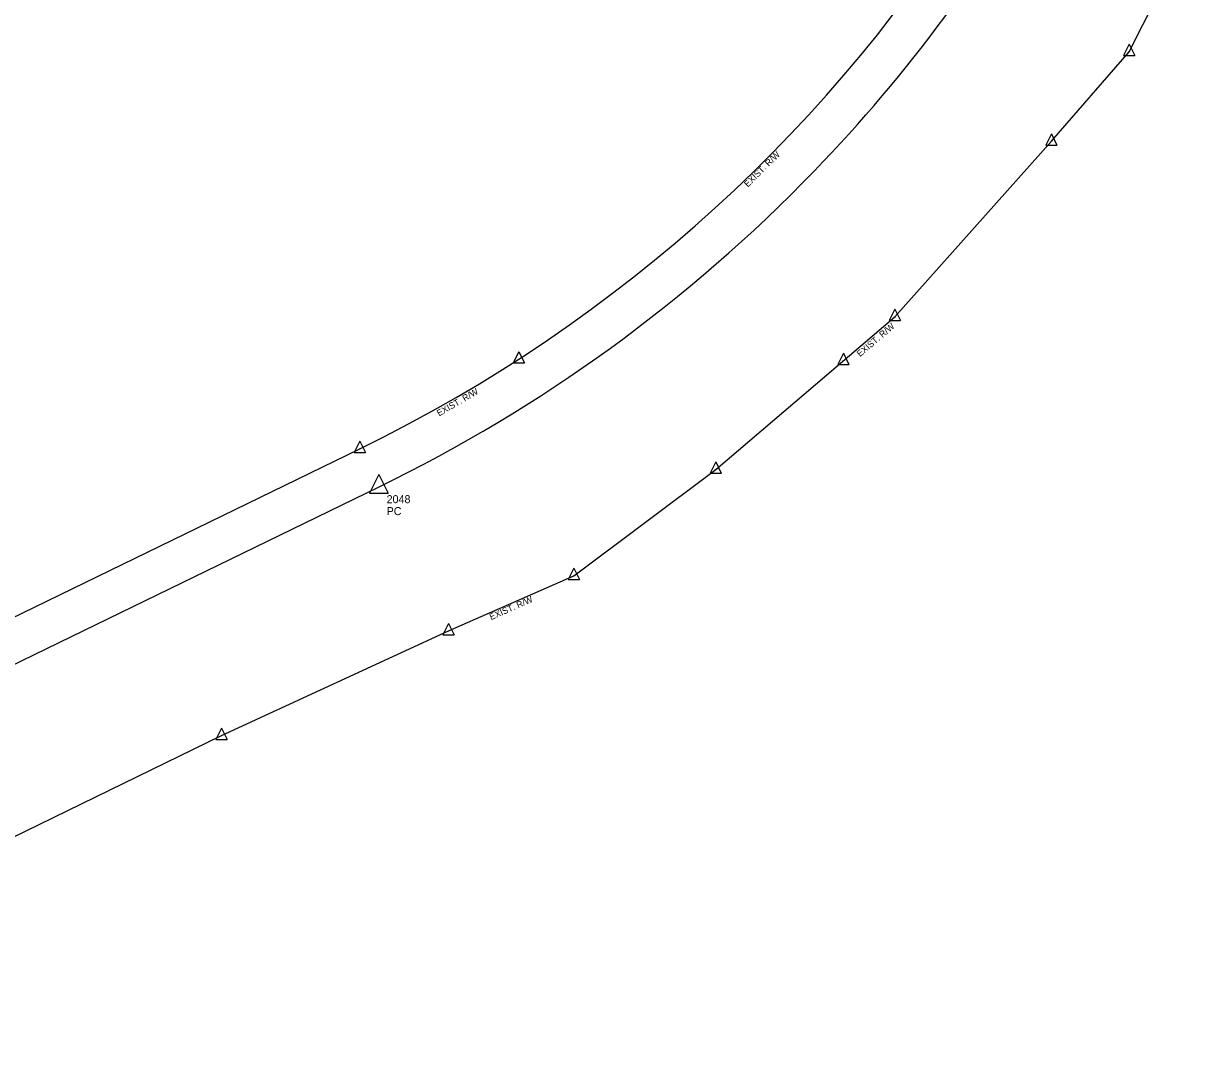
# Model space of a CAD drawing. Extents: x 1674300 to 1677561, y 225056 to 231852.
# Drawn here: x 1676229 to 1677337, y 227146 to 228119 of the extents above; entities that cross this region are included whole.
import ezdxf

# ---------------------------------------------------------------- set-up
doc = ezdxf.new("R2010")
doc.units = 0
for name, color, linetype in [('R_Annotation', 7, 'Continuous'), ('S_CAL_CORNER', 7, 'Continuous'), ('S_CAL_CORNER_ANNOT', 7, 'Continuous'), ('S_EXIST_ROW', 7, 'Continuous'), ('S_EXISTING_ALIGNMENT', 7, 'Continuous')]:
    doc.layers.add(name, color=color, linetype=linetype)

msp = doc.modelspace()

# ---------------------------------------------------------------- linework, layer by layer
at = {"layer": 'S_CAL_CORNER'}
for p, q in [((1676561.4, 227697), (1676552.6, 227679.3)), ((1676561.4, 227697), (1676552.6, 227679.3)), ((1676561.4, 227697), (1676552.6, 227679.3)), ((1676561.4, 227697), (1676552.6, 227679.3)), ((1676561.4, 227697), (1676570.1, 227679.3)), ((1676561.4, 227697), (1676570.1, 227679.3)), ((1676561.4, 227697), (1676570.1, 227679.3)), ((1676561.4, 227697), (1676570.1, 227679.3)), ((1676552.6, 227679.3), (1676570.1, 227679.3)), ((1676552.6, 227679.3), (1676570.1, 227679.3)), ((1676552.6, 227679.3), (1676570.1, 227679.3)), ((1676552.6, 227679.3), (1676570.1, 227679.3))]:
    msp.add_line(p, q, dxfattribs=at)
at = {"layer": 'S_EXIST_ROW'}
for p, q in [((1677264.8, 228093.1), (1677314.7, 228192.4)), ((1677264.8, 228100.2), (1677259.5, 228089.6)), ((1677264.8, 228100.2), (1677270.1, 228089.6)), ((1677192, 228009.2), (1677264.8, 228093.1)), ((1677259.5, 228089.6), (1677270.1, 228089.6)), ((1677264.8, 228093.1), (1677264.8, 228093.1)), ((1677045.3, 227844.6), (1677192, 228009.2)), ((1677192, 228016.3), (1677186.7, 228005.7)), ((1677192, 228016.3), (1677197.2, 228005.7)), ((1677192, 228009.2), (1677192, 228009.2)), ((1677186.7, 228005.7), (1677197.2, 228005.7)), ((1676877.3, 227701.7), (1677045.3, 227844.6)), ((1677045.3, 227851.7), (1677040, 227841.1)), ((1677040, 227841.1), (1677050.5, 227841.1)), ((1677045.3, 227851.7), (1677050.5, 227841.1)), ((1677045.3, 227844.6), (1677045.3, 227844.6)), ((1676692.6, 227812), (1676687.4, 227801.4)), ((1676692.6, 227812), (1676697.9, 227801.4)), ((1676997, 227810.6), (1676991.7, 227800)), ((1676997, 227810.6), (1677002.2, 227800)), ((1676687.4, 227801.4), (1676697.9, 227801.4)), ((1676692.6, 227804.9), (1676692.6, 227804.9)), ((1676991.7, 227800), (1677002.2, 227800)), ((1676996.9, 227803.5), (1676996.9, 227803.5)), ((1676060.3, 227485.8), (1676543.8, 227721)), ((1676543.8, 227728.1), (1676538.5, 227717.5)), ((1676543.8, 227728.1), (1676549, 227717.5)), ((1676543.8, 227721), (1676543.8, 227721)), ((1676538.5, 227717.5), (1676549, 227717.5)), ((1676877.3, 227708.8), (1676872, 227698.2)), ((1676877.3, 227708.8), (1676882.5, 227698.2)), ((1676744.4, 227601.9), (1676877.3, 227701.7)), ((1676872, 227698.2), (1676882.5, 227698.2)), ((1676877.3, 227701.7), (1676877.3, 227701.7)), ((1676744.4, 227609), (1676739.1, 227598.3)), ((1676744.4, 227609), (1676749.6, 227598.3)), ((1676626.9, 227550.2), (1676744.4, 227601.9)), ((1676739.1, 227598.3), (1676749.6, 227598.3)), ((1676744.4, 227601.9), (1676744.4, 227601.9)), ((1676626.9, 227557.3), (1676621.6, 227546.6)), ((1676626.9, 227557.3), (1676632.2, 227546.6)), ((1676414, 227452.1), (1676626.9, 227550.2)), ((1676621.6, 227546.6), (1676632.2, 227546.6)), ((1676626.9, 227550.2), (1676626.9, 227550.2)), ((1676414, 227459.2), (1676408.7, 227448.6)), ((1676414, 227459.2), (1676419.2, 227448.6)), ((1675784.5, 227145.9), (1676414, 227452.1)), ((1676408.7, 227448.6), (1676419.2, 227448.6)), ((1676414, 227452.1), (1676414, 227452.1))]:
    msp.add_line(p, q, dxfattribs=at)
for centre, radius in [((1677264.8, 228093.1), 0.18), ((1677264.8, 228093.1), 0.09), ((1677192, 228009.2), 0.18), ((1677192, 228009.2), 0.09), ((1677045.3, 227844.6), 0.18), ((1677045.3, 227844.6), 0.09), ((1676692.6, 227804.9), 0.18), ((1676692.6, 227804.9), 0.09), ((1676996.9, 227803.5), 0.18), ((1676996.9, 227803.5), 0.09), ((1676543.8, 227721), 0.18), ((1676543.8, 227721), 0.09), ((1676877.3, 227701.7), 0.18), ((1676877.3, 227701.7), 0.09), ((1676744.4, 227601.9), 0.18), ((1676744.4, 227601.9), 0.09), ((1676626.9, 227550.2), 0.18), ((1676626.9, 227550.2), 0.09), ((1676414, 227452.1), 0.18), ((1676414, 227452.1), 0.09)]:
    msp.add_circle(centre, radius, dxfattribs=at)
msp.add_arc((1675926.7, 228989.4), 1410.5, 295.9436, 0.8568, dxfattribs=at)
at = {"layer": 'S_EXISTING_ALIGNMENT'}
msp.add_line((1676112.4, 227466.7), (1676561.3, 227685), dxfattribs=at)
for start, end in [(315.9886, 345.8132), (295.9436, 315.9886)]:
    msp.add_arc((1675926.7, 228989.4), 1450.5, start, end, dxfattribs=at)

# ---------------------------------------------------------------- texts
at = {"layer": 'R_Annotation'}
for rotation, p in [(44.7136, (1676907.4, 227965.8)), (40.3857, (1677012.6, 227806.8)), (30.1458, (1676618, 227751.2)), (23.7616, (1676666.8, 227560.3))]:
    msp.add_text('EXIST. R/W', height=6, rotation=rotation, dxfattribs=at).set_placement(p)
at = {"layer": 'S_CAL_CORNER_ANNOT'}
for s, p in [('2048', (1676568.8, 227670)), ('2048', (1676568.8, 227670)), ('2048', (1676568.8, 227670)), ('2048', (1676568.8, 227670)), ('PC', (1676568.8, 227658.8)), ('PC', (1676568.8, 227658.8)), ('PC', (1676568.8, 227658.8)), ('PC', (1676568.8, 227658.8))]:
    msp.add_text(s, height=7.5, dxfattribs=at).set_placement(p)

doc.saveas('drawing.dxf')
